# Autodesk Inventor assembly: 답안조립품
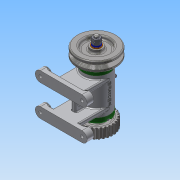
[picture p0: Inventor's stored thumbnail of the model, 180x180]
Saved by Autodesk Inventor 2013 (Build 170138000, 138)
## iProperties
Created: 2015-11
Part Number: 답안조립품
Document SubType Name: Assembly
Designer: Administrator
Author: Administrator
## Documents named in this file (16)
- C:\Users\Administrator\Desktop\451110V1053\답안조립품.iam
- C:\Users\Administrator\Desktop\451110V1053\본체.ipt
- C:\Users\Administrator\Desktop\451110V1053\V벨트풀리.ipt
- C:\Users\Administrator\Desktop\451110V1053\너트 M 8.ipt
- C:\Users\Administrator\Desktop\451110V1053\니플 M 6 x 0.75.ipt
- C:\Users\Administrator\Desktop\451110V1053\베어링 15 x 32 x 9.ipt
- C:\Users\Administrator\Desktop\451110V1053\볼트 M 6 x 8.ipt
- C:\Users\Administrator\Desktop\451110V1053\볼트 M4 x 12.ipt
- C:\Users\Administrator\Desktop\451110V1053\스퍼기어.ipt
- C:\Users\Administrator\Desktop\451110V1053\스프링와셔 8.ipt
- C:\Users\Administrator\Desktop\451110V1053\오일 실 15 25 7.ipt
- C:\Users\Administrator\Desktop\451110V1053\와셔 6x11.5.ipt
- C:\Users\Administrator\Desktop\451110V1053\와셔 8x17.ipt
- C:\Users\Administrator\Desktop\451110V1053\축.ipt
- C:\Users\Administrator\Desktop\451110V1053\커버.ipt
- C:\Users\Administrator\Desktop\451110V1053\키 3 x 3 x 12.ipt
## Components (11 placed, 3 different names)
1. V벨트풀리:1
2. KS B 2023 6002 - 15 x 32 x 9:1
3. KS B 2023 6002 - 15 x 32 x 9:2
4. ISO 4762 M4 x 12:2
5. ISO 4762 M4 x 12:3
6. ISO 4762 M4 x 12:4
7. ISO 4762 M4 x 12:5
8. ISO 4762 M4 x 12:1
9. ISO 4762 M4 x 12:6
10. ISO 4762 M4 x 12:7
11. ISO 4762 M4 x 12:8
